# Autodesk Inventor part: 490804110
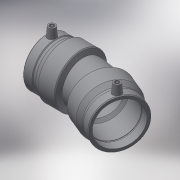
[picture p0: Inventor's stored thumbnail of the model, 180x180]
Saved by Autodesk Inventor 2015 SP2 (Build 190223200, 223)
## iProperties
Created: 2017-06
Part Number: 490804110
Material: Generic
Description: PLASSON 22.5° ELBOW 110
Document SubType Name: Modeling
Designer: KIM
Mass: 55.0731 g
Surface Area: 148.067 cm^2
Volume: 55.0731 cm^3
Density: 1 g/cm^3
Appearance: Default
Author: KIM
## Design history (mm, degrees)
derived "490804.ipt"
feature "Solid1::490804.ipt"
tag "TaggingFeature1"
body "Solid1"
other parameters: "d14" = 17.6296, "d19" = 3.52592, "d20" = 168 deg, "d22" = 131.56, "d23" = 143, "d24" = 127.6132, "d29" = 81, "d35" = 15, "d39" = 5 deg, "d45" = 4, "d46" = 14, "d47" = 0, "d67" = 45 deg, "d71" = 157.5 deg, "d75" = 7.15, "d82" = 45 deg, "d83" = 71, "d84" = 128.7, "d94" = 157.5 deg, "d95" = 63.8066, "d98" = 232, "d99" = 69.6, "d105" = 20.59, "d106" = 5.1475, "L_" = 232, "L_1" = 71, "D_" = 143, "A_" = 81, "d_2" = 12
